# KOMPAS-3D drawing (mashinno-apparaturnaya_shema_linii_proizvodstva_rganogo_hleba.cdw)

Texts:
  ОУП-02068108-260601-96-2010
  Машинно-аппаратурная схема  линии производства  ржаного хлеба
  Игорь
  Пар
  Сжатый воздух
  Вода
  Дрожжи
  Соль
  Мука
  Солод
  Тесто
  Уходящие газы
  Хлеб
  Машинно-аппаратурная схема
  линии производства
  ржаного хлеба
  Саранов И.А.
  Рязанов А.Н.
  УП-02068108-260601-2010-
Dimensions and other numbers on the sheet: 4; 5; 6; 7; 8; 1; 2; 3; 18; 19; 20; 13; 9; 10; 11; 12; 14; 15; 16; 21; 30; 24; 22; 23; 25; 26; 27; 28; 29; 33; 31; 32; 17; 36; 35; 34; 37; 38; 39; 40; 41; 42; 43; 0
